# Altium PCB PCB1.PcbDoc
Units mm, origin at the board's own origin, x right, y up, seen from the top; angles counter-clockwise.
Board outline 99.19 x 24.89 mm, 2 copper layers (Top Layer, Bottom Layer); 11 components, 30 nets, 78 pads, 3 vias.
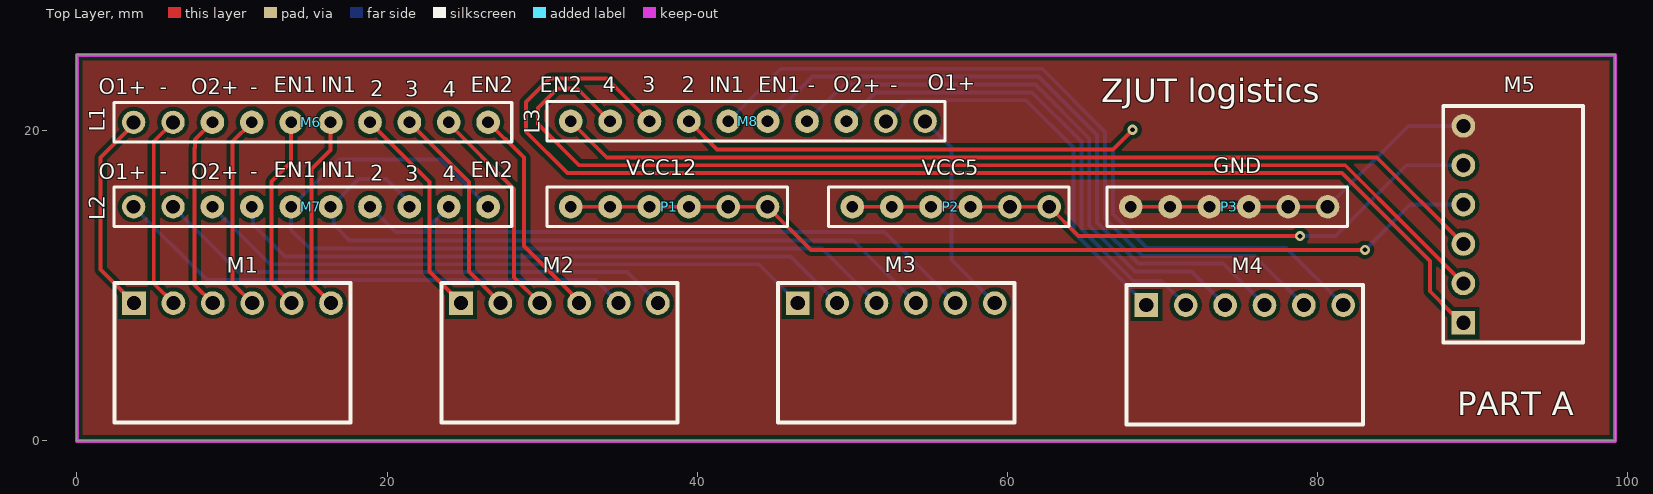
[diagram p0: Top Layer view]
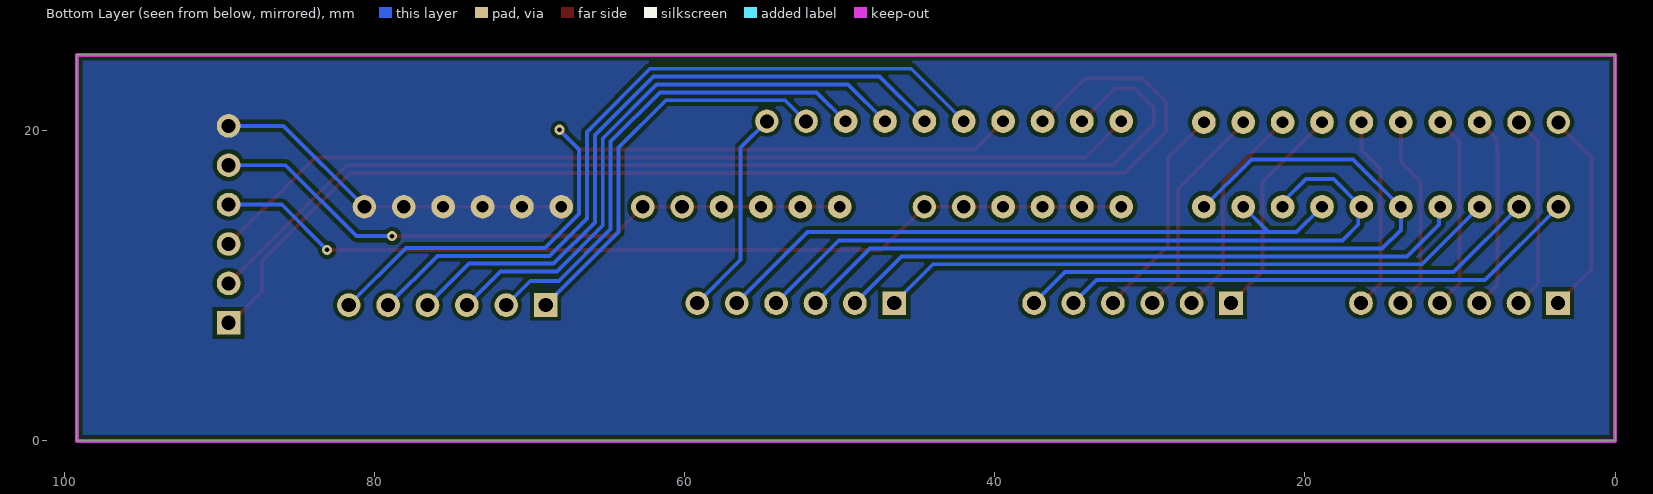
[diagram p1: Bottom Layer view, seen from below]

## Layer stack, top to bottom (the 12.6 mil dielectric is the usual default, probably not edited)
Top Solder: solder mask 0.0102, Solder Resist, Dk 3.5
Top Layer: signal copper 0.0356
Dielectric 1: dielectric 0.32, FR-4, Dk 4.8
Bottom Layer: signal copper 0.0356
Bottom Solder: solder mask 0.0102, Solder Resist, Dk 3.5

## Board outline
0,0 0,24.892 99.187,24.892 99.187,0

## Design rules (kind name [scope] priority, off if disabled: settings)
Clearance [All] p1: gap=0.254 ignorepadtopadclearanceinfootprint=FALSE except(0: Arc-Hole Track-Hole SMDPad-Hole THPad-Hole Via-Hole Fill-Hole Poly-Hole Region-Hole Text-Hole)
PolygonConnect [All] p1: thpad.connectstyle=Direct thpad.reliefconductorwidth=0.254 thpad.reliefentries=4 thpad.polygonreliefangle="90 Angle" thpad.airgapwidth=0.254 smdpad.connectstyle=Relief smdpad.reliefconductorwidth=0.254 smdpad.reliefentries=4 smdpad.polygonreliefangle="90 Angle" smdpad.airgapwidth=0.254 via.connectstyle=Direct via.reliefconductorwidth=0.254 via.reliefentries=4 via.polygonreliefangle="90 Angle" via.airgapwidth=0.254
RoutingVias [All] p1: holewidth=0.711 width=1.27 viastyle="Through Hole" minholewidth=0.711 minwidth=1.27 maxholewidth=0.711 maxwidth=1.27
SolderMaskExpansion [All] p1: expansion=0.102 istentingtop=FALSE
Width [All] p1: maxlimit=1.016 minlimit=0.127 preferedwidth=0.254 minimp=50.000000 maximp=50.000000 favimp=50.000000
30 further rules are at their usual default settings.

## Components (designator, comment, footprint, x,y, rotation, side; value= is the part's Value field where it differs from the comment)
M1 "H2.54X6" Header6 -6.223,33.067 r0 top
M2 "H2.54X6" Header6 14.859,33.067 r0 top
M3 "H2.54X6" Header6 36.576,33.067 r0 top
M4 "H2.54X6" Header6 59.055,32.94 r0 top
M5 "H2.54X6" Header6 65.231,-2.286 r90 top
M6 "L289N" HDR1X10 3.656,20.548 r0 top
M7 "L289N" HDR1X10 3.656,15.103 r0 top
M8 "L289N" HDR1X10 54.699,20.615 r180 top
P1 "HEADER_6" HDR1X6 44.539,15.103 r180 top
P2 "HEADER_6" HDR1X6 62.701,15.103 r180 top
P3 "HEADER_6" HDR1X6 80.652,15.103 r180 top

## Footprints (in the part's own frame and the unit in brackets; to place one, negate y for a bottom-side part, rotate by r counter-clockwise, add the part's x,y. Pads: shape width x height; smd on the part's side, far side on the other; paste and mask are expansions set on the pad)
HDR1X6 [mil]
  round 59.06 hole 35.43: 1(0,0) 2(100,0)
  round 60 hole 30: 3(200,0) 4(300,0) 5(400,0) 6(500,0)
  silkscreen extent -50,-50 560,50
HDR1X10 [mil]
  round 59.06 hole 35.43: 1(0,0) 2(100,0)
  round 60 hole 30: 3(200,0) 4(300,0) 5(400,0) 6(500,0) 7(600,0) 8(700,0) 9(800,0) 10(900,0)
  silkscreen extent -50,-50 960,50
Header6 [mil]
  rect 60x60 hole 36: 1(390,-951.85)
  round 60 hole 36: 2(490,-951.85) 3(590,-951.85) 4(690,-951.85) 5(790,-951.85) 6(890,-951.85)
  silkscreen extent 340,-1255 940,-901

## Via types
v1: diameter 0.65, hole 0.3, Top Layer to Bottom Layer, 3 vias

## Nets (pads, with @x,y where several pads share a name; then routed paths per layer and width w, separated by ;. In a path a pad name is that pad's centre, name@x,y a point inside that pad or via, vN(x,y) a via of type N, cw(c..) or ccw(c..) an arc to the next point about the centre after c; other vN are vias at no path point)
GND: M5.6 P3.1 P3.2 P3.3 P3.4 P3.5 P3.6 | length 23.6
  Top Layer w0.254: P3.6 P3.5 P3.4 P3.3 P3.2 P3.1
  Bottom Layer w0.254: P3.1 85.869,20.32 M5.6
M1_EN1: M1.5 M6.5 | length 12.7
  Top Layer w0.254: M6.5 13.816,17.989 12.551,16.724 12.551,10.182 M1.5
M1_EN2: M2.4 M6.10 | length 14.1
  Top Layer w0.254: M6.10 27.588,19.476 27.641,19.476 28.829,18.288 28.829,12.573 32.385,9.017 M2.4
M1_IN1: M1.6 M6.6 | length 12.7
  Top Layer w0.254: M6.6 16.356,18.769 15.113,17.526 15.113,10.16 M1.6
M1_IN2: M2.1 M6.7 | length 14.1
  Top Layer w0.254: M6.7 22.733,16.711 22.733,10.922 M2.1
M1_IN3: M2.2 M6.8 | length 14.1
  Top Layer w0.254: M6.8 25.273,16.711 25.273,10.922 M2.2
M1_IN4: M2.3 M6.9 | length 14.1
  Top Layer w0.254: M6.9 23.976,20.474 28.194,16.256 28.194,10.541 M2.3
M1_OUT1+: M1.1 M6.1 | length 13.4
  Top Layer w0.254: M6.1 3.656,20.42 1.524,18.288 1.524,11.049 M1.1
M1_OUT1-: M1.2 M6.2 | length 12.7
  Top Layer w0.254: M6.2 4.953,19.305 4.953,10.16 M1.2
M1_OUT2+: M1.3 M6.3 | length 12.6
  Top Layer w0.254: M6.3 7.62,19.432 7.62,18.923 7.593,18.896 7.593,10.06 M1.3
M1_OUT2-: M1.4 M6.4 | length 12.7
  Top Layer w0.254: M6.4 10.033,19.305 10.033,10.16 M1.4
M2_EN1: M3.3 M7.5 M7.10 | length 56.4
  Bottom Layer w0.254: M7.10 23.458,18.161 16.891,18.161 13.833,15.103 M7.5 13.816,13.616 15.021,12.411 48.041,12.411 M3.3
M2_IN1: M3.4 M7.6 M7.8 | length 47.6
  Bottom Layer w0.254: M7.8 21.436,15.394 19.939,16.891 18.161,16.891 16.373,15.103 M7.6 16.559,14.9 16.559,13.96 17.588,12.93 50.062,12.93 M3.4
M2_IN2: M3.5 M7.7 M7.9 | length 42.6
  Bottom Layer w0.254: M7.7 20.537,13.462 22.335,13.462 ; M7.9 22.335,13.462 ; M3.5 52.07,13.462 22.335,13.462
M2_OUT1+: M2.5 M7.1 | length 33.8
  Bottom Layer w0.254: M7.1 8.38,10.379 33.436,10.379 M2.5
M2_OUT1-: M2.6 M7.2 | length 33.8
  Bottom Layer w0.254: M7.2 10.412,10.887 35.468,10.887 M2.6
M2_OUT2+: M3.1 M7.3 | length 40.3
  Bottom Layer w0.254: M7.3 12.444,11.395 43.977,11.395 M3.1
M2_OUT2-: M3.2 M7.4 | length 40.9
  Bottom Layer w0.254: M7.4 11.352,15.027 11.352,13.96 13.408,11.903 46.009,11.903 M3.2
M3_EN1: M4.4 M8.5 | length 42.6
  Bottom Layer w0.254: M8.5 47.42,23.495 62.016,23.495 65.786,19.725 65.786,14.093 68.449,11.43 73.914,11.43 M4.4
M3_EN2: M5.3 M8.10 | length 60.8
  Top Layer w0.254: M8.10 34.166,18.288 83.82,18.288 M5.3
M3_IN1: M4.5 M8.6 | length 48.1
  Bottom Layer w0.254: M8.6 45.388,24.003 62.226,24.003 66.294,19.935 66.294,14.351 68.707,11.938 75.946,11.938 M4.5
M3_IN2: M4.6 M8.7 | length 53.1
  Top Layer w0.254: M8.7 41.278,18.796 66.802,18.796 v1(68.072,20.066)
  Bottom Layer w0.254: v1(68.072,20.066) 66.802,18.796 66.802,14.637 68.993,12.446 77.978,12.446 M4.6
M3_IN3: M5.1 M8.8 | length 78.3
  Top Layer w0.254: M8.8 34.166,23.368 30.48,23.368 28.956,21.844 28.956,19.939 31.623,17.272 81.578,17.272 87.249,11.601 87.249,9.652 88.646,8.255 88.773,8.255 M5.1
M3_IN4: M5.2 M8.9 | length 71
  Top Layer w0.254: M8.9 32.261,22.733 30.988,22.733 29.718,21.463 29.718,20.447 32.385,17.78 81.788,17.78 85.963,13.605 M5.2
M3_OUT1+: M3.6 M8.1 | length 13.6
  Bottom Layer w0.254: M8.1 56.388,18.926 56.388,11.684 M3.6
M3_OUT1-: M4.1 M8.2 | length 26
  Bottom Layer w0.254: M8.2 53.516,21.971 61.214,21.971 64.262,18.923 64.262,13.462 M4.1
M3_OUT2+: M4.2 M8.3 | length 31.6
  Bottom Layer w0.254: M8.3 51.484,22.479 61.595,22.479 64.77,19.304 64.77,13.672 68.114,10.329 69.935,10.329 M4.2
M3_OUT2-: M4.3 M8.4 | length 37.1
  Bottom Layer w0.254: M8.4 49.452,22.987 61.805,22.987 65.278,19.514 65.278,13.883 68.239,10.922 71.882,10.922 M4.3
VCC5: M5.5 P2.1 P2.2 P2.3 P2.4 P2.5 P2.6 | length 42.1
  Top Layer w0.254: P2.6 P2.5 P2.4 P2.3 P2.2 P2.1 64.596,13.208 v1(78.867,13.208)
  Bottom Layer w0.254: v1(78.867,13.208) 81.153,13.208 85.725,17.78 M5.5
VCC12: M5.4 P1.1 P1.2 P1.3 P1.4 P1.5 P1.6 | length 59.9
  Top Layer w0.254: P1.6 P1.5 P1.4 P1.3 P1.2 P1.1 47.323,12.319 v1(83.058,12.319)
  Bottom Layer w0.254: v1(83.058,12.319) 85.979,15.24 M5.4

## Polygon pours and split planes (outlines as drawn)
no net on Top Overlay "NONET_L-01_P-001" (solid): 0,24.892
GND on Top Layer "GND_L01_P000" (solid, pour order 0): 0,24.892 0,0 99.187,0 99.187,24.892
GND on Bottom Layer "GND_L02_P001" (solid, pour order 1): 0,24.892 0,0 99.187,0 99.187,24.892

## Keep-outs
Keep-Out Layer:
  the board outline again, w0.254

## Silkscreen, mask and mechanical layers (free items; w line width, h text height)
Top Overlay:
  text "O1+" at 54.864,22.606 h1
  text "EN1" at 12.7,22.479 h1
  text "IN1" at 15.748,22.479 h1
  text "EN2" at 25.4,22.479 h1
  text "EN2" at 29.845,22.479 h1
  text "4" at 33.909,22.479 h1
  text "3" at 36.449,22.479 h1
  text "2" at 38.989,22.479 h1
  text "IN1" at 40.767,22.479 h1
  text "EN1" at 43.942,22.479 h1
  text "-" at 47.117,22.487 h1
  text "O2+" at 48.768,22.479 h1
  text "-" at 52.451,22.487 h1
  text "O1+" at 1.397,22.352 h1
  text "-" at 5.334,22.36 h1
  text "O2+" at 7.366,22.352 h1
  text "-" at 11.176,22.36 h1
  text "2" at 18.923,22.225 h1
  text "3" at 21.167,22.208 h1
  text "4" at 23.58,22.208 h1
  text "ZJUT logistics" at 66.04,21.844 h1.52
  text "L1" at 1.778,19.939 h1 r90
  text "L3" at 29.845,19.812 h1 r90
  text "GND" at 73.279,17.272 h1
  text "VCC12" at 35.433,17.145 h1
  text "VCC5" at 54.483,17.145 h1
  text "EN1" at 12.7,17.018 h1
  text "IN1" at 15.748,17.018 h1
  text "EN2" at 25.4,17.018 h1
  text "O1+" at 1.397,16.891 h1
  text "-" at 5.334,16.899 h1
  text "O2+" at 7.366,16.891 h1
  text "-" at 11.176,16.899 h1
  text "2" at 18.923,16.764 h1
  text "3" at 21.167,16.747 h1
  text "4" at 23.58,16.747 h1
  text "L2" at 1.778,14.224 h1 r90
  text "PART A" at 89.027,1.651 h1.52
